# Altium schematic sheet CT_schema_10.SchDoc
size 388 x 278 mm
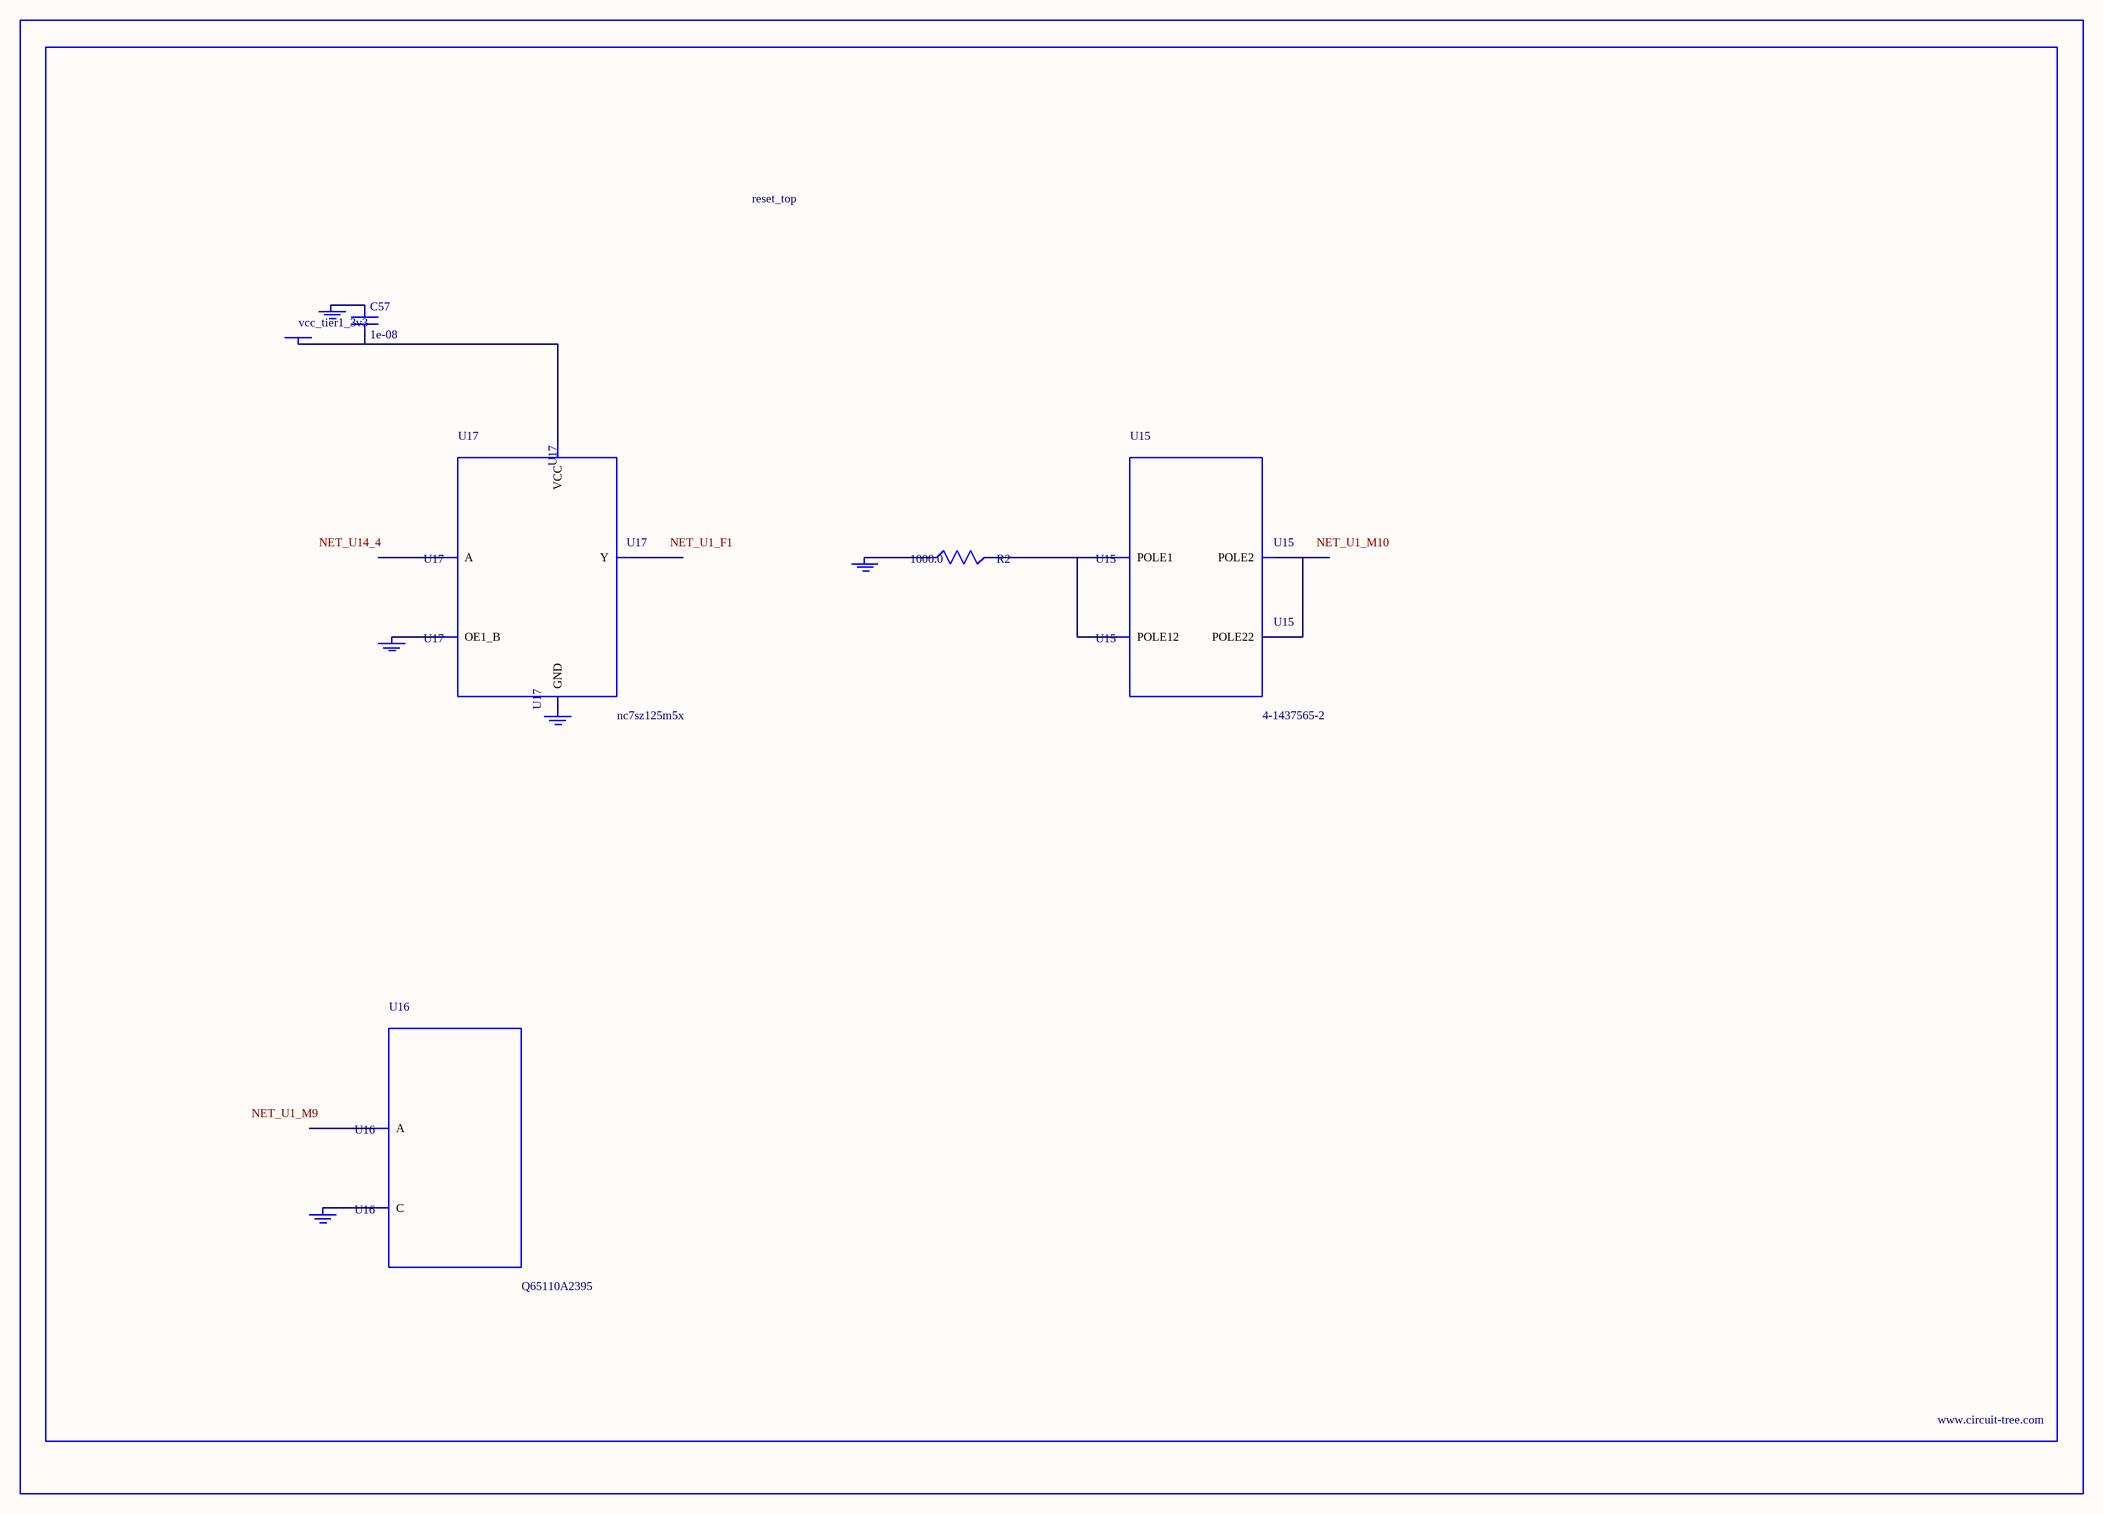
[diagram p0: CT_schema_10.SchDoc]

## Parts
BORDER9  (no value)
C57  1e-08  [C0402]
GND_INSTANCE_9_0  (no value)
GND_INSTANCE_9_1  (no value)
GND_INSTANCE_9_2  (no value)
GND_INSTANCE_9_3  (no value)
GND_INSTANCE_9_4  (no value)
POWER_INSTANCE_9_0  vcc_tier1_3v3
R2  1000.0  [R0603]
U15  4-1437565-2  [SW_4-1437565-2]
U16  Q65110A2395  [LGM67K-G1J2-24-Z]
U17  nc7sz125m5x  [NC7SZ125M5X]

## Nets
NetC57_1: C57.1 GND_INSTANCE_9_2.0(GND)
NetC57_2: C57.2 POWER_INSTANCE_9_0.0(PWR) U17.5(VCC)
NetGND_INSTANCE_9_0_0: GND_INSTANCE_9_0.0(GND) R2.1
NetGND_INSTANCE_9_1_0: GND_INSTANCE_9_1.0(GND) U16.C
NetGND_INSTANCE_9_3_0: GND_INSTANCE_9_3.0(GND) U17.1(OE1_B)
NetGND_INSTANCE_9_4_0: GND_INSTANCE_9_4.0(GND) U17.3(GND)
NetR2_2: R2.2 U15.1(POLE1) U15.2(POLE12)
NetU15_3: U15.3(POLE2) U15.4(POLE22)

Not connected (* = marked no-connect by the designer): U16 A; U17 2(A) 4(Y)

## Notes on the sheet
- Labels drawn without touching a wire or pin: NET_U1_F1, NET_U1_M9, NET_U1_M10, NET_U14_4

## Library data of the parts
BORDER9 = BORDER_PAGE9
C57 = C0402C103K3RAC
GND_INSTANCE_9_0-GND_INSTANCE_9_4 = GND
POWER_INSTANCE_9_0 = PWR
R2 = RC0603JR-071KL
